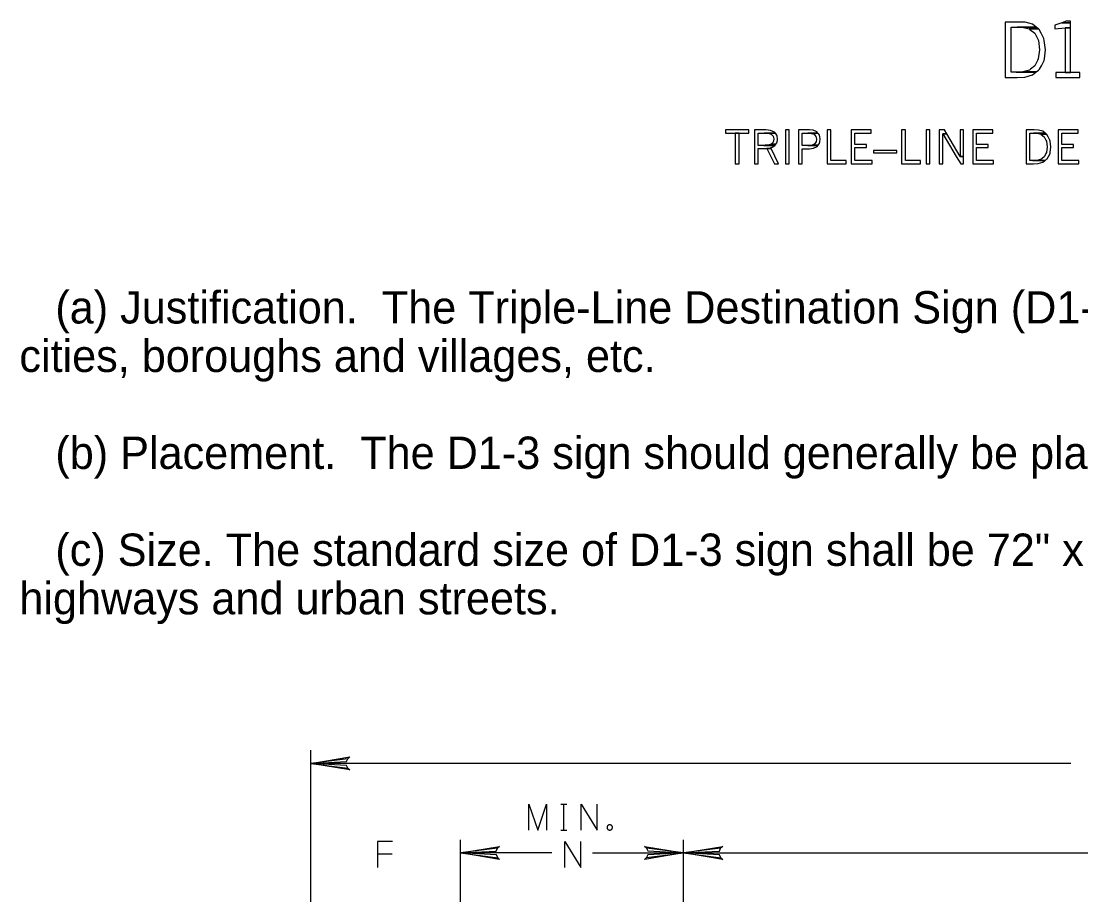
# Model space of a CAD drawing. Extents: x 0.013 to 0.187, y -0.092 to 0.261.
# Drawn here: x 0.0266 to 0.1086, y 0.1928 to 0.2609 of the extents above; entities that cross this region are included whole.
import ezdxf

# ---------------------------------------------------------------- set-up
doc = ezdxf.new("R2010")
doc.units = 0
for name, color, linetype in [('1', 7, 'Continuous'), ('2', 7, 'Continuous'), ('3', 7, 'Continuous')]:
    doc.layers.add(name, color=color, linetype=linetype)

msp = doc.modelspace()

# ---------------------------------------------------------------- linework, layer by layer
at = {"layer": '1'}
for points in [[(0.102751, 0.256562), (0.102751, 0.256526), (0.103666, 0.256526), (0.10426, 0.256562), (0.104854, 0.256741), (0.105119, 0.256947), (0.103218, 0.256947), (0.103218, 0.256972), (0.103218, 0.257102), (0.103218, 0.257171), (0.103218, 0.257439), (0.103218, 0.257841), (0.103218, 0.257985), (0.103218, 0.258672), (0.103218, 0.258675), (0.103218, 0.259396), (0.103218, 0.259539), (0.103218, 0.25995), (0.103218, 0.260253), (0.103218, 0.260283), (0.103218, 0.260403), (0.103218, 0.260422), (0.105147, 0.260422), (0.104846, 0.26065), (0.104283, 0.260797), (0.103771, 0.260822), (0.102751, 0.260822), (0.102751, 0.260797), (0.102751, 0.26065), (0.102751, 0.260422), (0.102751, 0.260403), (0.102751, 0.260283), (0.102751, 0.260253), (0.102751, 0.25995), (0.102751, 0.259539), (0.102751, 0.259396), (0.102751, 0.258675), (0.102751, 0.258672), (0.102751, 0.257985), (0.102751, 0.257841), (0.102751, 0.257439), (0.102751, 0.257171), (0.102751, 0.257102), (0.102751, 0.256972), (0.102751, 0.256947), (0.102751, 0.256741)], [(0.107465, 0.260884), (0.107134, 0.260753), (0.107812, 0.260753), (0.107812, 0.260884)], [(0.104156, 0.260403), (0.104606, 0.260283), (0.10533, 0.260283), (0.105172, 0.260403), (0.105147, 0.260422), (0.103665, 0.260422)], [(0.104617, 0.257102), (0.104118, 0.256972), (0.105151, 0.256972), (0.105319, 0.257102), (0.105408, 0.257171), (0.105548, 0.257439), (0.105758, 0.257841), (0.105778, 0.257985), (0.105869, 0.258672), (0.10587, 0.258675), (0.105767, 0.259396), (0.105747, 0.259539), (0.10553, 0.25995), (0.105371, 0.260253), (0.10533, 0.260283), (0.104606, 0.260283), (0.104646, 0.260253), (0.105038, 0.25995), (0.105241, 0.259539), (0.105312, 0.259396), (0.1054, 0.258675), (0.105401, 0.258672), (0.10531, 0.257985), (0.105239, 0.257841), (0.105041, 0.257439), (0.104703, 0.257171)], [(0.10659, 0.260379), (0.10659, 0.26029), (0.107386, 0.260379), (0.107812, 0.260379), (0.107812, 0.260588), (0.107812, 0.260753), (0.107134, 0.260753), (0.10659, 0.260588)], [(0.107386, 0.26029), (0.107386, 0.256911), (0.107812, 0.256911), (0.107812, 0.26029), (0.107812, 0.260379), (0.107386, 0.260379)], [(0.104118, 0.256972), (0.103599, 0.256947), (0.105119, 0.256947), (0.105151, 0.256972)], [(0.106663, 0.256911), (0.106663, 0.256526), (0.108516, 0.256526), (0.108516, 0.256911)], [(0.081086, 0.252474), (0.081086, 0.252222), (0.082915, 0.252222), (0.082915, 0.252474)], [(0.081851, 0.252222), (0.081851, 0.249848), (0.082149, 0.249848), (0.082149, 0.252222)], [(0.083349, 0.251038), (0.083349, 0.249848), (0.083635, 0.249848), (0.083635, 0.251038), (0.084623, 0.251038), (0.084589, 0.251107), (0.084702, 0.251146), (0.084908, 0.251262), (0.084923, 0.251282), (0.083635, 0.251282), (0.083635, 0.251286), (0.083635, 0.251303), (0.083635, 0.251377), (0.083635, 0.251483), (0.083635, 0.251531), (0.083635, 0.251755), (0.083635, 0.251778), (0.083635, 0.251988), (0.083635, 0.252073), (0.083635, 0.252149), (0.083635, 0.252214), (0.083635, 0.252227), (0.083635, 0.252229), (0.084947, 0.252229), (0.084881, 0.252309), (0.084577, 0.25244), (0.084229, 0.25247), (0.084087, 0.252474), (0.083349, 0.252474), (0.083349, 0.25247), (0.083349, 0.25244), (0.083349, 0.252309), (0.083349, 0.252229), (0.083349, 0.252227), (0.083349, 0.252214), (0.083349, 0.252149), (0.083349, 0.252073), (0.083349, 0.251988), (0.083349, 0.251778), (0.083349, 0.251755), (0.083349, 0.251531), (0.083349, 0.251483), (0.083349, 0.251377), (0.083349, 0.251303), (0.083349, 0.251286), (0.083349, 0.251282), (0.083349, 0.251262), (0.083349, 0.251146), (0.083349, 0.251107)], [(0.084205, 0.252227), (0.084412, 0.252214), (0.08496, 0.252214), (0.08495, 0.252227), (0.084949, 0.252227), (0.084947, 0.252229), (0.084084, 0.252229)], [(0.084742, 0.251483), (0.084632, 0.251377), (0.084996, 0.251377), (0.085078, 0.251483), (0.085087, 0.251531), (0.085131, 0.251755), (0.085135, 0.251778), (0.085095, 0.251988), (0.085078, 0.252073), (0.085014, 0.252149), (0.08496, 0.252214), (0.084412, 0.252214), (0.08464, 0.252149), (0.084714, 0.252073), (0.084796, 0.251988), (0.084837, 0.251778), (0.084841, 0.251755), (0.084792, 0.251531)], [(0.085739, 0.252474), (0.085739, 0.249848), (0.086033, 0.249848), (0.086033, 0.252474)], [(0.086756, 0.251021), (0.086756, 0.249848), (0.087038, 0.249848), (0.087038, 0.251021), (0.0876, 0.251021), (0.0879, 0.251057), (0.088184, 0.251189), (0.088247, 0.251267), (0.08704, 0.251267), (0.08704, 0.251268), (0.08704, 0.251297), (0.08704, 0.251391), (0.08704, 0.251427), (0.08704, 0.251545), (0.08704, 0.251759), (0.08704, 0.25176), (0.08704, 0.251969), (0.08704, 0.252078), (0.08704, 0.252135), (0.08704, 0.252209), (0.08704, 0.252227), (0.08704, 0.252228), (0.088256, 0.252228), (0.088178, 0.252322), (0.087896, 0.252443), (0.087602, 0.252472), (0.087517, 0.252474), (0.086756, 0.252474), (0.086756, 0.252472), (0.086756, 0.252443), (0.086756, 0.252322), (0.086756, 0.252228), (0.086756, 0.252227), (0.086756, 0.252209), (0.086756, 0.252135), (0.086756, 0.252078), (0.086756, 0.251969), (0.086756, 0.25176), (0.086756, 0.251759), (0.086756, 0.251545), (0.086756, 0.251427), (0.086756, 0.251391), (0.086756, 0.251297), (0.086756, 0.251268), (0.086756, 0.251267), (0.086756, 0.251189), (0.086756, 0.251057)], [(0.088, 0.251391), (0.087818, 0.251297), (0.08827, 0.251297), (0.088346, 0.251391), (0.088375, 0.251427), (0.088397, 0.251545), (0.088436, 0.251759), (0.088436, 0.25176), (0.088399, 0.251969), (0.08838, 0.252078), (0.088332, 0.252135), (0.088271, 0.252209), (0.088257, 0.252227), (0.088256, 0.252228), (0.087462, 0.252228), (0.08756, 0.252227), (0.087765, 0.252209), (0.08796, 0.252135), (0.088008, 0.252078), (0.088101, 0.251969), (0.088139, 0.25176), (0.088138, 0.251759), (0.088107, 0.251545), (0.088025, 0.251427)], [(0.088957, 0.2501), (0.088957, 0.249848), (0.090427, 0.249848), (0.090427, 0.2501), (0.089253, 0.2501), (0.089253, 0.252474), (0.088957, 0.252474)], [(0.09083, 0.2501), (0.09083, 0.249848), (0.09244, 0.249848), (0.09244, 0.2501), (0.091118, 0.2501), (0.091118, 0.251105), (0.092011, 0.251105), (0.092011, 0.251349), (0.091118, 0.251349), (0.091118, 0.252226), (0.092378, 0.252226), (0.092378, 0.252474), (0.09083, 0.252474), (0.09083, 0.252226), (0.09083, 0.251349), (0.09083, 0.251105)], [(0.094732, 0.2501), (0.094732, 0.249848), (0.096202, 0.249848), (0.096202, 0.2501), (0.095029, 0.2501), (0.095029, 0.252474), (0.094732, 0.252474)], [(0.096623, 0.252474), (0.096623, 0.249848), (0.096917, 0.249848), (0.096917, 0.252474)], [(0.097639, 0.250424), (0.097639, 0.249848), (0.097912, 0.249848), (0.097912, 0.250424), (0.097912, 0.252171), (0.098228, 0.252171), (0.098051, 0.252474), (0.097639, 0.252474), (0.097639, 0.252171)], [(0.098959, 0.250424), (0.099304, 0.249848), (0.099529, 0.249848), (0.099529, 0.250424), (0.099256, 0.250424), (0.098228, 0.252171), (0.097912, 0.252171)], [(0.099256, 0.252474), (0.099256, 0.250424), (0.099529, 0.250424), (0.099529, 0.252474)], [(0.100235, 0.2501), (0.100235, 0.249848), (0.101844, 0.249848), (0.101844, 0.2501), (0.100523, 0.2501), (0.100523, 0.251105), (0.101416, 0.251105), (0.101416, 0.251349), (0.100523, 0.251349), (0.100523, 0.252226), (0.101783, 0.252226), (0.101783, 0.252474), (0.100235, 0.252474), (0.100235, 0.252226), (0.100235, 0.251349), (0.100235, 0.251105)], [(0.104376, 0.24987), (0.104376, 0.249848), (0.104936, 0.249848), (0.105299, 0.24987), (0.105662, 0.249979), (0.105824, 0.250106), (0.104662, 0.250106), (0.104662, 0.250121), (0.104662, 0.2502), (0.104662, 0.250242), (0.104662, 0.250406), (0.104662, 0.250652), (0.104662, 0.25074), (0.104662, 0.25116), (0.104662, 0.251161), (0.104662, 0.251603), (0.104662, 0.25169), (0.104662, 0.251941), (0.104662, 0.252126), (0.104662, 0.252144), (0.104662, 0.252217), (0.104662, 0.252229), (0.105841, 0.252229), (0.105657, 0.252369), (0.105313, 0.252459), (0.105, 0.252474), (0.104376, 0.252474), (0.104376, 0.252459), (0.104376, 0.252369), (0.104376, 0.252229), (0.104376, 0.252217), (0.104376, 0.252144), (0.104376, 0.252126), (0.104376, 0.251941), (0.104376, 0.25169), (0.104376, 0.251603), (0.104376, 0.251161), (0.104376, 0.25116), (0.104376, 0.25074), (0.104376, 0.250652), (0.104376, 0.250406), (0.104376, 0.250242), (0.104376, 0.2502), (0.104376, 0.250121), (0.104376, 0.250106), (0.104376, 0.249979)], [(0.105235, 0.252217), (0.105511, 0.252144), (0.105953, 0.252144), (0.105856, 0.252217), (0.105841, 0.252229), (0.104935, 0.252229)], [(0.105517, 0.2502), (0.105212, 0.250121), (0.105843, 0.250121), (0.105946, 0.2502), (0.106, 0.250242), (0.106086, 0.250406), (0.106214, 0.250652), (0.106226, 0.25074), (0.106282, 0.25116), (0.106283, 0.251161), (0.10622, 0.251603), (0.106208, 0.25169), (0.106075, 0.251941), (0.105978, 0.252126), (0.105953, 0.252144), (0.10551, 0.252144), (0.105534, 0.252126), (0.105774, 0.251941), (0.105898, 0.25169), (0.105941, 0.251603), (0.105996, 0.251161), (0.105996, 0.25116), (0.105941, 0.25074), (0.105897, 0.250652), (0.105776, 0.250406), (0.10557, 0.250242)], [(0.106838, 0.2501), (0.106838, 0.249848), (0.108447, 0.249848), (0.108447, 0.2501), (0.107126, 0.2501), (0.107126, 0.251105), (0.108019, 0.251105), (0.108019, 0.251349), (0.107126, 0.251349), (0.107126, 0.252226), (0.108386, 0.252226), (0.108386, 0.252474), (0.106838, 0.252474), (0.106838, 0.252226), (0.106838, 0.251349), (0.106838, 0.251105)], [(0.084168, 0.251286), (0.084073, 0.251282), (0.084923, 0.251282), (0.084926, 0.251286), (0.084939, 0.251303), (0.084996, 0.251377), (0.084632, 0.251377), (0.084393, 0.251303)], [(0.08431, 0.251038), (0.084886, 0.249848), (0.085206, 0.249848), (0.084623, 0.251038)], [(0.087587, 0.251268), (0.087483, 0.251267), (0.088247, 0.251267), (0.088247, 0.251268), (0.08827, 0.251297), (0.087817, 0.251297)], [(0.092548, 0.250892), (0.092548, 0.250703), (0.094363, 0.250703), (0.094363, 0.250892)], [(0.105212, 0.250121), (0.104895, 0.250106), (0.105824, 0.250106), (0.105843, 0.250121)]]:
    msp.add_lwpolyline(points, close=True, dxfattribs=at)
at = {"layer": '3'}
for p, q in [((0.049001, 0.197558), (0.049001, 0.204488)), ((0.049001, 0.20348), (0.052025, 0.203981)), ((0.05187, 0.203837), (0.049001, 0.20348)), ((0.049001, 0.20348), (0.051769, 0.203623)), ((0.107815, 0.20348), (0.049001, 0.20348)), ((0.051771, 0.203321), (0.049001, 0.20348)), ((0.049001, 0.20348), (0.051878, 0.203104)), ((0.052025, 0.202973), (0.049001, 0.20348)), ((0.051769, 0.203623), (0.05187, 0.203837)), ((0.052025, 0.203981), (0.05187, 0.203837)), ((0.051878, 0.203104), (0.051771, 0.203321)), ((0.051878, 0.203104), (0.052025, 0.202973)), ((0.049001, 0.19277), (0.049001, 0.197558)), ((0.060593, 0.19277), (0.060593, 0.197558)), ((0.060593, 0.19655), (0.063617, 0.197051)), ((0.063462, 0.196907), (0.060593, 0.19655)), ((0.063361, 0.196693), (0.063462, 0.196907)), ((0.063617, 0.197051), (0.063462, 0.196907)), ((0.074979, 0.196927), (0.074831, 0.197058)), ((0.074831, 0.197058), (0.077855, 0.19655)), ((0.074979, 0.196927), (0.075086, 0.19671)), ((0.077855, 0.19655), (0.074979, 0.196927)), ((0.077855, 0.19277), (0.077855, 0.197558)), ((0.077855, 0.19655), (0.080879, 0.197051)), ((0.080724, 0.196907), (0.077855, 0.19655)), ((0.080623, 0.196693), (0.080724, 0.196907)), ((0.080879, 0.197051), (0.080724, 0.196907)), ((0.060593, 0.19655), (0.063361, 0.196693)), ((0.067649, 0.19655), (0.060593, 0.19655)), ((0.063363, 0.196391), (0.060593, 0.19655)), ((0.060593, 0.19655), (0.06347, 0.196174)), ((0.063617, 0.196043), (0.060593, 0.19655)), ((0.06347, 0.196174), (0.063363, 0.196391)), ((0.06347, 0.196174), (0.063617, 0.196043)), ((0.070799, 0.19655), (0.077855, 0.19655)), ((0.077855, 0.19655), (0.074831, 0.19605)), ((0.074831, 0.19605), (0.074987, 0.196193)), ((0.074987, 0.196193), (0.077855, 0.19655)), ((0.075088, 0.196408), (0.074987, 0.196193)), ((0.075086, 0.19671), (0.077855, 0.19655)), ((0.077855, 0.19655), (0.075088, 0.196408)), ((0.077855, 0.19655), (0.080623, 0.196693)), ((0.077855, 0.19655), (0.116033, 0.19655)), ((0.080625, 0.196391), (0.077855, 0.19655)), ((0.077855, 0.19655), (0.080732, 0.196174)), ((0.080879, 0.196043), (0.077855, 0.19655)), ((0.080732, 0.196174), (0.080625, 0.196391)), ((0.080732, 0.196174), (0.080879, 0.196043))]:
    msp.add_line(p, q, dxfattribs=at)
for points in [[(0.065885, 0.198314), (0.065885, 0.200331), (0.066584, 0.198314), (0.067235, 0.200331), (0.067235, 0.198314)], [(0.068346, 0.200331), (0.068822, 0.200331)], [(0.068584, 0.198314), (0.068584, 0.200331)], [(0.069918, 0.198314), (0.069918, 0.200331), (0.071172, 0.198314), (0.071172, 0.200331)], [(0.072347, 0.198521), (0.072346, 0.198542), (0.072342, 0.198564), (0.072337, 0.198584), (0.072329, 0.198605), (0.072319, 0.198624), (0.072307, 0.198642), (0.072294, 0.198659), (0.072279, 0.198674), (0.072262, 0.198688), (0.072244, 0.198699), (0.072224, 0.198709), (0.072204, 0.198717), (0.072183, 0.198723), (0.072162, 0.198726), (0.07214, 0.198727), (0.072119, 0.198726), (0.072098, 0.198723), (0.072077, 0.198717), (0.072057, 0.198709), (0.072037, 0.198699), (0.072019, 0.198688), (0.072002, 0.198674), (0.071987, 0.198659), (0.071974, 0.198642), (0.071962, 0.198624), (0.071952, 0.198605), (0.071944, 0.198584), (0.071939, 0.198564), (0.071935, 0.198542), (0.071934, 0.198521), (0.071935, 0.198499), (0.071939, 0.198478), (0.071944, 0.198457), (0.071952, 0.198437), (0.071962, 0.198418), (0.071974, 0.198399), (0.071987, 0.198383), (0.072002, 0.198367), (0.072019, 0.198354), (0.072037, 0.198342), (0.072057, 0.198332), (0.072077, 0.198325), (0.072098, 0.198319), (0.072119, 0.198315), (0.07214, 0.198314), (0.072162, 0.198315), (0.072183, 0.198319), (0.072204, 0.198325), (0.072224, 0.198332), (0.072244, 0.198342), (0.072262, 0.198354), (0.072279, 0.198367), (0.072294, 0.198383), (0.072307, 0.198399), (0.072319, 0.198418), (0.072329, 0.198437), (0.072337, 0.198457), (0.072342, 0.198478), (0.072346, 0.198499), (0.072347, 0.198521)], [(0.068346, 0.198314), (0.068822, 0.198314)], [(0.055326, 0.197433), (0.054167, 0.197433), (0.054167, 0.195416)], [(0.068657, 0.195416), (0.068657, 0.197433), (0.069912, 0.195416), (0.069912, 0.197433)], [(0.054167, 0.196448), (0.054167, 0.196448)], [(0.05531, 0.196448), (0.054167, 0.196448)]]:
    msp.add_lwpolyline(points, dxfattribs=at)

# ---------------------------------------------------------------- texts
at = {"layer": '2'}
for s, p in [('   (a) Justification.  The Triple-Line Destination Sign (D1-3) shall be authorized to indicate the direction to', (0.026446, 0.237502)), ('cities, boroughs and villages, etc.', (0.026446, 0.233752)), ('   (b) Placement.  The D1-3 sign should generally be placed in advance of an intersection.', (0.026446, 0.226253)), ('   (c) Size. The standard size of D1-3 sign shall be 72" x 36".  The 48" x 24" size may be used on minor', (0.026446, 0.218753)), ('highways and urban streets.', (0.026446, 0.215004))]:
    msp.add_text(s, height=0.00249975, dxfattribs=at).set_placement(p)

doc.saveas('drawing.dxf')
